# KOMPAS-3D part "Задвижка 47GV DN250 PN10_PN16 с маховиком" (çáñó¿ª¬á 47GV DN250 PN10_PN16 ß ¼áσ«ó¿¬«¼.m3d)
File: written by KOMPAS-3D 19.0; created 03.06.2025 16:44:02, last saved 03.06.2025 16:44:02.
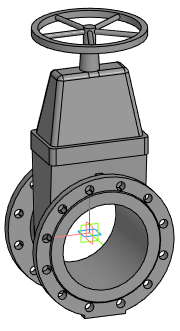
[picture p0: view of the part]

Document properties: Автор: Евгений; Полное имя файла: E:\Dendor Работа Сачек\3D для проекитирвщиков\2.1 Тип 47GV, 47GV.Z Задвижка клиновая фланцевая с обрезиненным клином\stp_Тип 47GV. Задвижка DN40-DN350 с маховиком\Задвижка 47GV DN250 PN10_PN16 с маховиком.m3d

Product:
- Part/product: Задвижка 47GV DN250 PN10_PN16 с маховиком

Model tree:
1. Операция без истории:1  (labels: Задвижка 47GV DN250 PN10_PN16 с маховиком)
